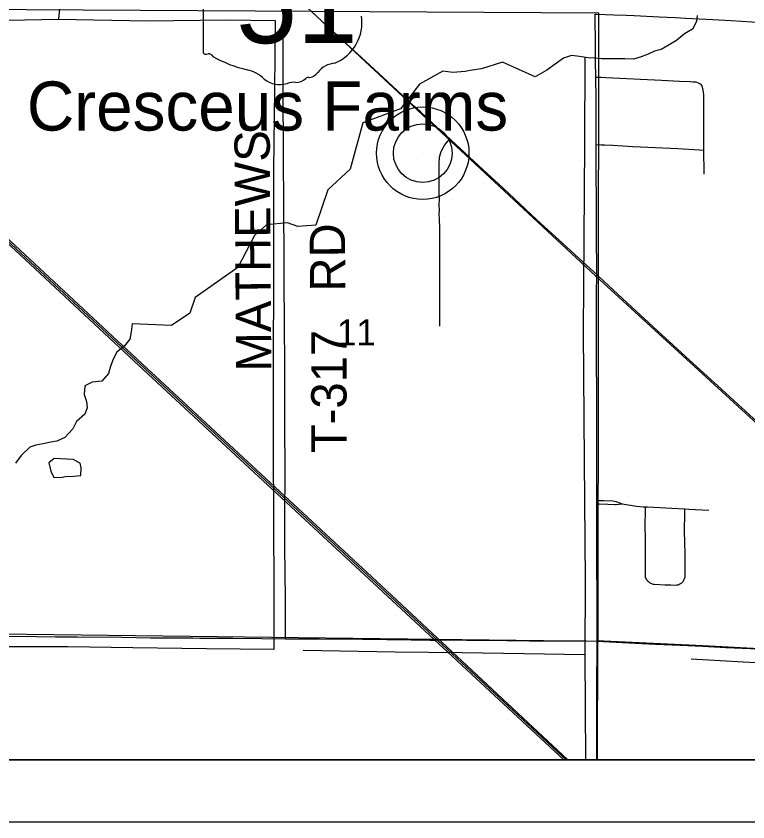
# Model space of a CAD drawing. Extents: x 0 to 40.2, y 0 to 22.
# Drawn here: x 6.836 to 8.013, y 14 to 15.297 of the extents above; entities that cross this region are included whole.
import ezdxf

# ---------------------------------------------------------------- set-up
doc = ezdxf.new("R2010")
doc.units = 0
for name, color, linetype in [('GM_X_Adjacent_County', 7, 'Continuous'), ('GM_X_City_Street', 7, 'Continuous'), ('GM_X_Corporation', 7, 'Continuous'), ('GM_X_County_Road_Text', 7, 'Continuous'), ('GM_X_Interstate_Route', 7, 'Continuous'), ('GM_X_Major_Lake', 7, 'Continuous'), ('GM_X_Major_River', 7, 'Continuous'), ('GM_X_Minor_Lake', 7, 'Continuous'), ('GM_X_Minor_Lake_Text', 7, 'Continuous'), ('GM_X_Rail_Line', 7, 'Continuous'), ('GM_X_State_Shield', 7, 'Continuous'), ('GM_X_Township_Road', 7, 'Continuous'), ('GM_X_Unincorporated', 7, 'Continuous'), ('GM_X_US_Shield', 7, 'Continuous')]:
    doc.layers.add(name, color=color, linetype=linetype)

msp = doc.modelspace()

# ---------------------------------------------------------------- linework, layer by layer
at = {"layer": 'GM_X_Adjacent_County'}
for p, q in [((2.1, 14.1), (8.9, 14.1)), ((2, 14), (9, 14))]:
    msp.add_line(p, q, dxfattribs=at)
at = {"layer": 'GM_X_Corporation'}
for points in [[(6.7593, 15.308), (7.7728, 15.3017), (7.7718, 14.2901), (6.7653, 14.3024)], [(6.7663, 14.1), (7.7713, 14.1), (7.7718, 14.2901), (6.7653, 14.3024)], [(7.7701, 14.1), (8.3972, 14.1), (8.3994, 14.2616), (8.2735, 14.2679), (8.2129, 14.2704), (8.1543, 14.2731), (8.0979, 14.2756), (8.0423, 14.2781), (7.9407, 14.2831), (7.7704, 14.2911)]]:
    msp.add_lwpolyline(points, close=True, dxfattribs=at)
for points in [[(2.1, 14.1), (8.7736, 14.1)], [(2.9469, 14.1), (8.7736, 14.1)]]:
    msp.add_lwpolyline(points, dxfattribs=at)
at = {"layer": 'GM_X_Interstate_Route'}
msp.add_line((7.1369, 15.4391), (7.1369, 15.2389), dxfattribs=at)
for centre, radius, start, end in [((7.3223, 15.2857), 0.0699, 292.3089, 8.9858), ((7.14, 15.2385), 0.00308, 171.9584, 258.3066), ((7.1404, 15.259), 0.0235, 267.339, 280.6039), ((7.1453, 15.2274), 0.00848, 29.7484, 93.2717), ((7.2523, 15.4072), 0.2019, 240.4129, 257.1985), ((7.1921, 15.149), 0.0632, 47.1842, 75.836), ((7.3518, 15.1828), 0.0383, 94.4031, 142.5768), ((7.2865, 15.2114), 0.0214, 268.777, 315.5493), ((7.3059, 15.192), 0.00601, 65.7517, 132.6484), ((7.3033, 15.2196), 0.0226, 282.8732, 323.2771), ((7.2604, 15.2264), 0.0401, 230.7004, 286.2918), ((7.2836, 15.1572), 0.0329, 85.6951, 111.2099)]:
    msp.add_arc(centre, radius, start, end, dxfattribs=at)
at = {"layer": 'GM_X_Major_Lake'}
for points in [[(7.7701, 14.8808), (7.7482, 14.9008), (7.7153, 14.9312), (7.6745, 14.9685), (7.619, 15.0202), (7.5938, 15.0434), (7.5801, 15.056), (7.5577, 15.0767), (7.5353, 15.0973), (7.5336, 15.0989), (7.513, 15.1181), (7.4866, 15.1426), (7.4782, 15.15), (7.4572, 15.1694), (7.4258, 15.1986), (7.4052, 15.2176), (7.385, 15.2359), (7.3757, 15.2447), (7.3557, 15.2633), (7.3376, 15.2796), (7.3095, 15.3058)], [(8.0305, 14.6418), (8.0285, 14.6437), (7.9907, 14.6779), (7.9651, 14.7015), (7.931, 14.7324), (7.8741, 14.7844), (7.8472, 14.8094), (7.8266, 14.8283), (7.8043, 14.8491), (7.7898, 14.8626), (7.7734, 14.8777), (7.7701, 14.8808)]]:
    msp.add_lwpolyline(points, dxfattribs=at)
at = {"layer": 'GM_X_Major_River'}
for points in [[(4.1455, 17.415), (4.1542, 17.4069), (4.3224, 17.2484), (4.5126, 17.0764), (4.6277, 16.9694), (4.7733, 16.8366), (5.084, 16.5474), (5.609, 16.0605), (6.0377, 15.6628), (6.1678, 15.5423), (6.5654, 15.1729), (7.036, 14.7358), (7.4144, 14.3845), (7.7209, 14.1)], [(4.1471, 17.4167), (4.1558, 17.4086), (4.3239, 17.2501), (4.5142, 17.0781), (4.6293, 16.9711), (4.7748, 16.8383), (5.0856, 16.5491), (5.6113, 16.0632), (6.0399, 15.6663), (6.1698, 15.5443), (6.5669, 15.1758), (7.0383, 14.7375), (7.4155, 14.3872), (7.7237, 14.1)], [(4.9799, 17.4209), (5.3025, 17.1358), (5.9504, 16.5554), (6.6271, 15.9327), (7.157, 15.4476), (7.7681, 14.8787), (8.2449, 14.4419), (8.6184, 14.1)], [(4.7243, 16.8813), (4.7752, 16.8317), (5.0824, 16.5458), (5.6074, 16.0588), (6.0352, 15.6606), (6.1639, 15.542), (6.5637, 15.1714), (7.0334, 14.7344), (7.4114, 14.3836), (7.7174, 14.1)]]:
    msp.add_lwpolyline(points, dxfattribs=at)
at = {"layer": 'GM_X_Minor_Lake'}
for points in [[(6.9059, 15.3135), (6.904, 15.2915)], [(6.7658, 15.2611), (6.7663, 15.2892), (6.904, 15.2915), (7.0466, 15.2892), (7.1741, 15.2906), (7.2524, 15.2897), (7.2518, 15.1778), (7.2501, 15.0495), (7.2499, 14.9611), (7.2499, 14.8659), (7.2496, 14.7505), (7.2496, 14.6071), (7.2499, 14.4819), (7.2504, 14.3741), (7.2504, 14.2773), (7.1423, 14.2787), (7.0235, 14.2799), (6.9191, 14.2815), (6.8113, 14.2818), (6.761, 14.2826), (6.7423, 14.2992)], [(7.932, 15.2977), (7.9307, 15.2879), (7.9244, 15.2758), (7.9115, 15.2681), (7.8984, 15.2573), (7.8866, 15.2502), (7.874, 15.2429), (7.863, 15.24), (7.8527, 15.2356), (7.8416, 15.2309), (7.8295, 15.2273), (7.8151, 15.2279), (7.8053, 15.228), (7.7917, 15.2279), (7.7784, 15.2281), (7.7663, 15.2287), (7.7561, 15.2296), (7.7425, 15.2317), (7.7293, 15.2334), (7.7168, 15.2291), (7.703, 15.2194), (7.69, 15.2098), (7.6713, 15.1987)], [(7.6713, 15.1987), (7.6183, 15.2227), (7.5848, 15.2119), (7.5666, 15.2091), (7.5583, 15.2073), (7.5386, 15.2061), (7.5224, 15.2079), (7.485, 15.1873), (7.4541, 15.1476), (7.3936, 15.1246), (7.3735, 15.0502), (7.3374, 15.017), (7.3179, 14.96), (7.2892, 14.9582), (7.2726, 14.9642), (7.2385, 14.9606), (7.2193, 14.9438), (7.1928, 14.8919), (7.1239, 14.8436), (7.1152, 14.8184), (7.0858, 14.7987), (7.0226, 14.8016)], [(7.7508, 15.2304), (7.7505, 15.0904), (7.7496, 14.9387), (7.7484, 14.7884), (7.75, 14.5808), (7.7515, 14.3884), (7.7508, 14.2689), (7.7518, 14.1)], [(7.0226, 14.8016), (7.0209, 14.7884), (7.0188, 14.777), (7.01, 14.7658), (6.9981, 14.7557), (6.9914, 14.7437), (6.9871, 14.7313), (6.9847, 14.7214), (6.9735, 14.7091), (6.958, 14.7074)], [(6.958, 14.7074), (6.9461, 14.7016), (6.9455, 14.6879), (6.9488, 14.6765), (6.9501, 14.6662), (6.9466, 14.656), (6.9331, 14.6445), (6.9269, 14.6324), (6.9142, 14.6186), (6.9012, 14.6127), (6.8917, 14.611), (6.8792, 14.6085), (6.8675, 14.6061), (6.858, 14.6032), (6.8441, 14.5897), (6.8348, 14.5774)], [(7.7508, 14.2689), (7.6532, 14.2705), (7.5534, 14.2721), (7.446, 14.273), (7.2977, 14.2758)], [(8.4489, 14.233), (8.4382, 14.2449), (8.2911, 14.2473), (8.1765, 14.2514), (8.0441, 14.2547), (7.9221, 14.2616)]]:
    msp.add_lwpolyline(points, dxfattribs=at)
at = {"layer": 'GM_X_Minor_Lake_Text'}
msp.add_line((6.9099, 14.5548), (6.9152, 14.5559), dxfattribs=at)
msp.add_lwpolyline([(6.9152, 14.5559), (6.928, 14.5562), (6.9398, 14.5573), (6.9406, 14.5698), (6.9391, 14.5774), (6.9275, 14.5832), (6.8968, 14.5849), (6.8885, 14.5777), (6.8914, 14.5641), (6.8966, 14.5542), (6.9099, 14.5548)], dxfattribs=at)
at = {"layer": 'GM_X_Rail_Line'}
for points in [[(7.2692, 14.2948), (7.2692, 14.3026), (7.2692, 14.3554), (7.2686, 14.4039), (7.2684, 14.4394), (7.2683, 14.4866), (7.2682, 14.5016), (7.2687, 14.5519), (7.2685, 14.5799), (7.2683, 14.6246), (7.2683, 14.6613), (7.2681, 14.6831), (7.2682, 14.7272), (7.2682, 14.7415), (7.2678, 14.7938), (7.2676, 14.8211), (7.2674, 14.851), (7.2674, 14.8895), (7.2671, 14.9218), (7.2668, 14.9734), (7.2667, 14.9989), (7.2664, 15.0219), (7.2662, 15.04), (7.2661, 15.0605), (7.266, 15.1065), (7.2656, 15.1469), (7.2656, 15.2116), (7.2656, 15.2309), (7.2656, 15.3066)], [(7.7688, 15.1984), (7.7682, 15.2248), (7.7679, 15.2379), (7.768, 15.2615), (7.7677, 15.2847), (7.7676, 15.2997)], [(7.7676, 15.2997), (7.7697, 15.2997), (7.7976, 15.2987), (7.8173, 15.298), (7.8304, 15.2975), (7.8708, 15.2954), (7.8962, 15.2941), (7.9136, 15.2931), (7.9564, 15.2912), (7.9863, 15.2896), (8.0197, 15.2874), (8.0854, 15.2836), (8.1096, 15.2821), (8.1425, 15.2805), (8.2207, 15.2758), (8.2548, 15.2741), (8.2715, 15.2735)], [(7.7693, 15.0898), (7.7693, 15.098), (7.7692, 15.1247), (7.769, 15.1695), (7.7689, 15.1925), (7.7688, 15.1984)], [(7.7688, 15.1984), (7.7772, 15.1982), (7.7846, 15.1979), (7.8746, 15.1935), (7.9032, 15.1921), (7.9206, 15.1913), (7.9252, 15.191), (7.9295, 15.1906), (7.9325, 15.1896), (7.936, 15.1881), (7.9386, 15.1858)], [(7.9427, 15.081), (7.9426, 15.1153), (7.9424, 15.1377), (7.9425, 15.1564), (7.9423, 15.1695), (7.9418, 15.1745), (7.9409, 15.1795), (7.9402, 15.1821), (7.9386, 15.1858)], [(7.5179, 14.7978), (7.5178, 14.8114), (7.5179, 14.8244), (7.5175, 14.8545), (7.5178, 14.8669), (7.5178, 14.8758), (7.5176, 14.8815), (7.5177, 14.8881), (7.5175, 14.9055), (7.5175, 14.9164), (7.5175, 14.9269), (7.5178, 14.9393), (7.5177, 14.9456), (7.5176, 14.9513), (7.5175, 14.9595), (7.5172, 14.9658), (7.5172, 14.9691), (7.5168, 14.9791), (7.5169, 14.9827), (7.5167, 14.9945), (7.5169, 15.0012), (7.5167, 15.0125), (7.5165, 15.0206), (7.5165, 15.0299), (7.5165, 15.0392), (7.5166, 15.0478), (7.5165, 15.0534), (7.5167, 15.0616), (7.5169, 15.0671), (7.5172, 15.0696), (7.518, 15.0732), (7.5194, 15.0773), (7.5213, 15.0818), (7.5233, 15.0857), (7.5258, 15.0893), (7.5281, 15.0922), (7.5336, 15.0989)], [(7.7701, 14.8808), (7.7702, 14.8979), (7.7697, 14.9315), (7.7697, 14.9818), (7.7697, 15.0005), (7.7694, 15.0434), (7.7694, 15.0682), (7.7693, 15.0837), (7.7693, 15.0898)], [(7.7693, 15.0898), (7.7775, 15.0895), (7.7825, 15.0893), (7.7961, 15.0887), (7.8285, 15.0869), (7.8646, 15.085), (7.9006, 15.0833), (7.9354, 15.0814), (7.9427, 15.081)], [(7.9429, 15.0425), (7.9429, 15.0537), (7.9427, 15.0718), (7.9427, 15.081)], [(7.7701, 14.5117), (7.7701, 14.5146), (7.7701, 14.517), (7.7702, 14.5444), (7.7703, 14.5922), (7.7701, 14.6624), (7.7701, 14.6873), (7.7703, 14.7022), (7.7699, 14.7295), (7.7699, 14.7749), (7.7698, 14.801), (7.7699, 14.8439), (7.77, 14.8563), (7.7701, 14.8743), (7.7701, 14.8808)], [(7.7701, 14.517), (7.7743, 14.517), (7.781, 14.517), (7.7962, 14.5164), (7.7986, 14.5161), (7.801, 14.5157), (7.8113, 14.5119)], [(7.7701, 14.5117), (7.7748, 14.5116), (7.7878, 14.511), (7.7992, 14.5106), (7.8015, 14.5107), (7.8113, 14.5119)], [(7.7709, 14.2909), (7.7707, 14.3069), (7.7707, 14.3212), (7.7707, 14.3691), (7.7705, 14.4095), (7.7703, 14.4425), (7.7701, 14.4972), (7.7701, 14.5117)], [(7.8113, 14.5119), (7.8339, 14.5081), (7.8446, 14.5071), (7.848, 14.5069)], [(7.848, 14.5069), (7.8479, 14.4984), (7.8478, 14.4801), (7.8479, 14.4518), (7.8479, 14.4217), (7.8479, 14.3963), (7.848, 14.3951), (7.8483, 14.394), (7.8487, 14.3926), (7.8492, 14.3914), (7.8501, 14.3902), (7.851, 14.3891), (7.8521, 14.3878), (7.8533, 14.3867), (7.8546, 14.3857), (7.8558, 14.3848), (7.8569, 14.3842), (7.8581, 14.3836), (7.8595, 14.3831), (7.8611, 14.3827), (7.8626, 14.3824), (7.8805, 14.3816), (7.8895, 14.3812), (7.8981, 14.381), (7.8995, 14.3813), (7.9011, 14.3817), (7.9024, 14.3822), (7.9037, 14.3828), (7.9049, 14.3834), (7.9059, 14.3841), (7.9071, 14.3849), (7.908, 14.3859), (7.9091, 14.387), (7.9098, 14.3879), (7.9105, 14.3891), (7.9111, 14.3903), (7.9116, 14.3914), (7.912, 14.3929), (7.9122, 14.3942), (7.9124, 14.3953), (7.9123, 14.4019), (7.9122, 14.4158), (7.9122, 14.4329), (7.9119, 14.4478), (7.9116, 14.4689), (7.9117, 14.4962), (7.9117, 14.5036)], [(7.848, 14.5069), (7.852, 14.5067), (7.8911, 14.5048), (7.9117, 14.5036), (7.9184, 14.5032), (7.9504, 14.5016)], [(6.7653, 14.2996), (6.7766, 14.2996), (6.8238, 14.2988), (6.8686, 14.2983), (6.899, 14.2979), (6.9345, 14.2977), (7.0054, 14.297), (7.052, 14.2963), (7.0688, 14.2964), (7.0881, 14.2964), (7.0974, 14.2963), (7.1204, 14.2959), (7.1316, 14.2958), (7.1558, 14.2958), (7.1844, 14.2958), (7.2311, 14.2953), (7.2692, 14.2948)], [(7.2692, 14.2948), (7.2727, 14.2948), (7.3237, 14.2944), (7.3933, 14.2938), (7.4717, 14.293), (7.4928, 14.2927), (7.5021, 14.2926), (7.5108, 14.2926), (7.5202, 14.2927), (7.5295, 14.2927), (7.5606, 14.2925), (7.5742, 14.2925), (7.5805, 14.2924), (7.5885, 14.2924), (7.6619, 14.2914), (7.6837, 14.2915), (7.7042, 14.2914), (7.7456, 14.2913), (7.7532, 14.2911), (7.7709, 14.2909)], [(7.7705, 14.1), (7.7705, 14.1019), (7.7705, 14.2094), (7.7709, 14.2909)], [(7.7709, 14.2909), (7.8117, 14.2887), (7.8322, 14.2877), (7.8645, 14.2862), (7.9042, 14.2845), (7.9409, 14.2825), (7.9781, 14.2807), (8.044, 14.2777)]]:
    msp.add_lwpolyline(points, dxfattribs=at)
at = {"layer": 'GM_X_State_Shield'}
msp.add_line((7.4901, 15.076), (7.4901, 15.076), dxfattribs=at)
at = {"layer": 'GM_X_Township_Road'}
msp.add_lwpolyline([(2.1, 20.9), (8.9, 20.9), (8.9, 14.1), (2.1, 14.1)], close=True, dxfattribs=at)
at = {"layer": 'GM_X_Unincorporated'}
for radius in [0.0744, 0.0472]:
    msp.add_circle((7.4901, 15.076), radius, dxfattribs=at)

# ---------------------------------------------------------------- texts
at = {"layer": 'GM_X_City_Street'}
msp.add_text('11', height=0.04186, rotation=0, dxfattribs=at).set_placement((7.3523, 14.7667))
at = {"layer": 'GM_X_County_Road_Text'}
for s, rotation, p in [('MATHEWS', 90.4077, (7.2466, 14.7248)), ('RD', 90.495, (7.3658, 14.8536)), ('T-317', 90, (7.3675, 14.5933))]:
    msp.add_text(s, height=0.05682, rotation=rotation, dxfattribs=at).set_placement(p)
at = {"layer": 'GM_X_Interstate_Route'}
msp.add_text('51', height=0.13184, dxfattribs=at).set_placement((7.1896, 15.2531))
at = {"layer": 'GM_X_US_Shield'}
msp.add_text('Cresceus Farms', height=0.078977, rotation=0, dxfattribs=at).set_placement((6.8531, 15.1124))

doc.saveas('drawing.dxf')
